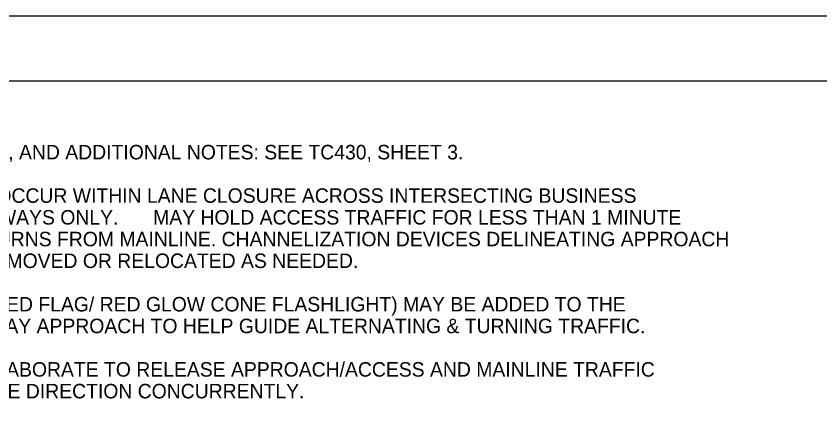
# Model space of a CAD drawing. Extents: x 99999.1 to 100095.7, y 99995 to 100010.7.
# Drawn here: x 100061.313 to 100065.2, y 100008.726 to 100010.687 of the extents above; entities that cross this region are included whole.
import ezdxf

# ---------------------------------------------------------------- set-up
doc = ezdxf.new("R2010")
doc.units = 0
for name, color, linetype in [('SH_GI_GeneralNotesBodyText', 7, 'Continuous'), ('SH_GI_PlotLimits', 7, 'Continuous'), ('SH_GI_SheetBorder', 7, 'Continuous')]:
    doc.layers.add(name, color=color, linetype=linetype)

msp = doc.modelspace()

# ---------------------------------------------------------------- linework, layer by layer
at = {"layer": 'SH_GI_PlotLimits'}
msp.add_lwpolyline([(100059.0625, 99999.6875), (100076.0625, 99999.6875), (100076.0625, 100010.6875), (100059.0625, 100010.6875)], close=True, dxfattribs=at)
at = {"layer": 'SH_GI_SheetBorder'}
msp.add_line((100060, 100010.375), (100075.75, 100010.375), dxfattribs=at)

# ---------------------------------------------------------------- texts
at = {"layer": 'SH_GI_GeneralNotesBodyText'}
for s, p in [('12. FOR LEGEND, TABLES, AND ADDITIONAL NOTES: SEE TC430, SHEET 3.', (100060.1, 100009.995)), ('13. WORK MAY BRIEFLY OCCUR WITHIN LANE CLOSURE ACROSS INTERSECTING BUSINESS ', (100060.1, 100009.785)), ('ACCESSES AND DRIVEWAYS ONLY. ', (100060.18, 100009.68)), ('MAY HOLD ACCESS TRAFFIC FOR LESS THAN 1 MINUTE', (100061.9762, 100009.68)), ('WHILE RESTRICTING TURNS FROM MAINLINE. CHANNELIZATION DEVICES DELINEATING APPROACH ', (100060.18, 100009.575)), ('OR ACCESS MAY BE REMOVED OR RELOCATED AS NEEDED.', (100060.18, 100009.47)), ('14. SINGLE AFAD (WITH RED FLAG/ RED GLOW CONE FLASHLIGHT) MAY BE ADDED TO THE ', (100060.1, 100009.26)), ('INTERSECTING ROADWAY APPROACH TO HELP GUIDE ALTERNATING & TURNING TRAFFIC.', (100060.18, 100009.155)), ('15. FLAGGERS MAY COLLABORATE TO RELEASE APPROACH/ACCESS AND MAINLINE TRAFFIC ', (100060.1, 100008.945)), ('TRAVELING IN THE SAME DIRECTION CONCURRENTLY.', (100060.18, 100008.84))]:
    msp.add_text(s, height=0.07, rotation=360, dxfattribs=at).set_placement(p)

doc.saveas('drawing.dxf')
